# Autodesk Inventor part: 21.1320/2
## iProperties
Created: 2006-12
Part Number: 21.1320/2
Document SubType Name: Modeling
Designer: Andy Moles
Material: Steel, Mild
Density: 7.86 g/cm^3
Mass: 5.5784 g
Surface Area: 8.43697 cm^2
Volume: 0.70972 cm^3
Description: M5 Square Nut With Position Fixing
Vendor: S
Author: Andy Moles
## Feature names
1. Extrusion1
2. Revolution1
3. Extrusion3
4. Fillet2
5. Fillet3
